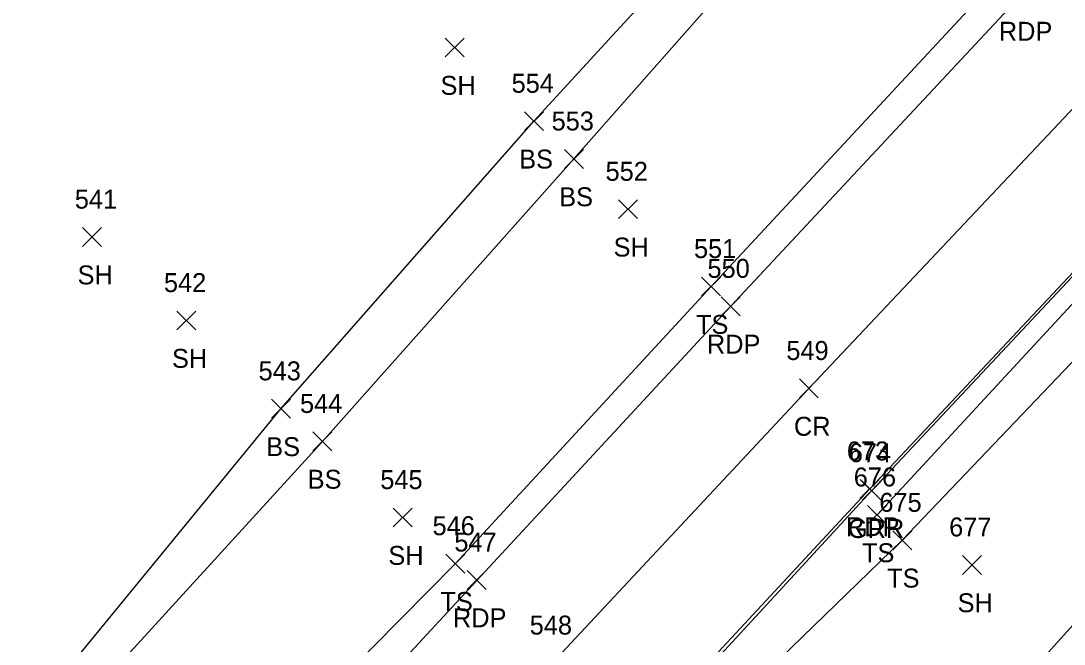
# Model space of a CAD drawing. Extents: x 1688195 to 1692013, y 424605 to 441234.
# Drawn here: x 1691404.7 to 1691514.7, y 438975.6 to 439041.4 of the extents above; entities that cross this region are included whole.
import ezdxf

# ---------------------------------------------------------------- set-up
doc = ezdxf.new("R2010")
doc.units = 0
for name, color, linetype in [('L_A', 7, 'Continuous'), ('L_I', 7, 'Continuous'), ('L_TIC', 7, 'Continuous'), ('LELB', 7, 'Continuous'), ('LFNC', 7, 'Continuous'), ('P_A', 7, 'Continuous'), ('P_I', 7, 'Continuous'), ('P_TIC', 7, 'Continuous'), ('PET', 7, 'Continuous'), ('PRC', 7, 'Continuous'), ('R_A', 7, 'Continuous'), ('R_I', 7, 'Continuous'), ('R_TIC', 7, 'Continuous'), ('RGR', 7, 'Continuous')]:
    doc.layers.add(name, color=color, linetype=linetype)

msp = doc.modelspace()

# ---------------------------------------------------------------- linework, layer by layer
at = {"layer": 'L_TIC'}
for points in [[(1691449.43, 439037.57), (1691451.43, 439039.57)], [(1691451.43, 439037.57), (1691449.43, 439039.57)], [(1691457.78, 439029.79), (1691459.78, 439031.79)], [(1691459.78, 439029.79), (1691457.78, 439031.79)], [(1691462, 439025.81), (1691464, 439027.81)], [(1691464, 439025.81), (1691462, 439027.81)], [(1691467.69, 439020.5), (1691469.69, 439022.5)], [(1691469.69, 439020.5), (1691467.69, 439022.5)], [(1691411.15, 439017.56), (1691413.15, 439019.56)], [(1691413.15, 439017.56), (1691411.15, 439019.56)], [(1691476.46, 439012.34), (1691478.46, 439014.34)], [(1691478.46, 439012.34), (1691476.46, 439014.34)], [(1691421.12, 439008.75), (1691423.12, 439010.75)], [(1691423.12, 439008.75), (1691421.12, 439010.75)], [(1691431.09, 438999.43), (1691433.09, 439001.43)], [(1691433.09, 438999.43), (1691431.09, 439001.43)], [(1691435.47, 438995.99), (1691437.47, 438997.99)], [(1691437.47, 438995.99), (1691435.47, 438997.99)], [(1691493.97, 438988.23), (1691495.97, 438990.23)], [(1691495.97, 438988.23), (1691493.97, 438990.23)], [(1691443.94, 438987.95), (1691445.94, 438989.95)], [(1691445.94, 438987.95), (1691443.94, 438989.95)], [(1691496.62, 438985.55), (1691498.62, 438987.55)], [(1691498.62, 438985.55), (1691496.62, 438987.55)], [(1691496.62, 438985.55), (1691498.62, 438987.55)], [(1691498.62, 438985.55), (1691496.62, 438987.55)], [(1691449.5, 438983.08), (1691451.5, 438985.08)], [(1691451.5, 438983.08), (1691449.5, 438985.08)], [(1691503.97, 438982.95), (1691505.97, 438984.95)], [(1691505.97, 438982.95), (1691503.97, 438984.95)]]:
    msp.add_lwpolyline(points, dxfattribs=at)
at = {"layer": 'LELB'}
for points in [[(1691372.73, 438902.64), (1691398.57, 438929.63), (1691421.61, 438954.81), (1691450.5, 438984.08), (1691477.46, 439013.34), (1691508.26, 439046.52), (1691540.85, 439082.44), (1691568.31, 439110.72), (1691593.69, 439141.21), (1691622.93, 439171.73), (1691652.84, 439206.76), (1691674.71, 439229.19), (1691701.22, 439256.48), (1691710.89, 439279.75), (1691723.95, 439307.99), (1691712.17, 439332.07), (1691693.94, 439358.26), (1691684, 439373.02)], [(1691358.65, 438915.95), (1691383.88, 438942.54), (1691406.19, 438968.83), (1691432.09, 439000.43), (1691458.78, 439030.79), (1691488.91, 439063.66), (1691516.55, 439102.83), (1691546.52, 439127.21), (1691571.44, 439162.09), (1691585.36, 439179.75), (1691595.61, 439189.84), (1691598.8, 439192.56), (1691623.09, 439224.33), (1691645.87, 439250.99)], [(1691362.51, 438912.64), (1691386.93, 438940.67), (1691409.23, 438967.09), (1691436.47, 438996.99), (1691463, 439026.81), (1691492.43, 439060.22), (1691523.16, 439097.82), (1691549.35, 439125.66), (1691575.52, 439158.24), (1691588.61, 439176.65), (1691597.67, 439188.52), (1691599.59, 439192.01), (1691624.28, 439223.08), (1691646.72, 439249.94), (1691645.87, 439250.99)], [(1691494.97, 438989.23), (1691529.39, 439026.47), (1691563.11, 439061.46), (1691592.32, 439093.25), (1691622.45, 439123.57), (1691640.28, 439144.55), (1691642.63, 439146.18), (1691644.54, 439148.64), (1691657.14, 439160.25), (1691677.5, 439185.53), (1691687.79, 439198.06), (1691700.53, 439206.6), (1691711.71, 439214.4), (1691729.93, 439221), (1691765.22, 439228.65), (1691785.8, 439230.06)], [(1691497.62, 438986.55), (1691532.48, 439023.13), (1691565.52, 439059.1), (1691594.4, 439089.96), (1691624.94, 439121.84), (1691642.24, 439143.61)], [(1691395.27, 438879.71), (1691419.93, 438903.79), (1691447.01, 438933.65), (1691476.59, 438966.16), (1691497.62, 438986.55)]]:
    msp.add_lwpolyline(points, dxfattribs=at)
at = {"layer": 'LFNC'}
msp.add_lwpolyline([(1691844.63, 439219.19), (1691827.3, 439208.18), (1691808.98, 439197.07), (1691805.18, 439194.78), (1691802.65, 439193.15), (1691780.93, 439179.95), (1691740.49, 439155.55), (1691707.63, 439134.9), (1691682.09, 439120.04), (1691638.96, 439093.47), (1691599.84, 439067.34), (1691566.38, 439033.38), (1691536.95, 439001.22), (1691500.89, 438961.26), (1691462.91, 438919.55), (1691429.39, 438883.14), (1691411.26, 438863.12)], dxfattribs=at)
at = {"layer": 'P_TIC'}
for points in [[(1691478.53, 439010.25), (1691480.53, 439012.25)], [(1691480.53, 439010.25), (1691478.53, 439012.25)], [(1691486.77, 439001.58), (1691488.77, 439003.58)], [(1691488.77, 439001.58), (1691486.77, 439003.58)], [(1691493.19, 438990.98), (1691495.19, 438992.98)], [(1691495.19, 438990.98), (1691493.19, 438992.98)], [(1691451.74, 438981.36), (1691453.74, 438983.36)], [(1691453.74, 438981.36), (1691451.74, 438983.36)]]:
    msp.add_lwpolyline(points, dxfattribs=at)
at = {"layer": 'PET'}
for points in [[(1691375.46, 438899.9), (1691401.5, 438927.23), (1691424.19, 438951.44), (1691479.53, 439011.25), (1691510.32, 439044.28), (1691543.27, 439079.53), (1691570.24, 439108.89), (1691596.97, 439137.86), (1691630.02, 439173.34), (1691657.32, 439202.46), (1691678.85, 439225.99), (1691705.09, 439253.29), (1691720.65, 439270.18), (1691741.75, 439292.31), (1691750.04, 439301.33), (1691750.82, 439305.81), (1691750.97, 439309.53)], [(1691392.15, 438883.12), (1691415.43, 438907.79), (1691443.51, 438937.17), (1691473.2, 438969.34), (1691494.19, 438991.98), (1691527.98, 439028.02), (1691561.01, 439063.43)]]:
    msp.add_lwpolyline(points, dxfattribs=at)
at = {"layer": 'PRC'}
msp.add_lwpolyline([(1691383.45, 438891.46), (1691410.11, 438918.45), (1691432.71, 438943.44), (1691460.69, 438973.59), (1691487.77, 439002.58), (1691519.39, 439036.11), (1691551.83, 439070.88), (1691579.21, 439100.29), (1691605.82, 439129.37), (1691637.88, 439164.38), (1691665.6, 439193.96), (1691687.96, 439216.92), (1691714.01, 439245.27), (1691730.35, 439261.96), (1691750.53, 439284.62), (1691763.38, 439297.71)], dxfattribs=at)
at = {"layer": 'R_TIC'}
for points in [[(1691493.4, 438990.79), (1691495.4, 438992.79)], [(1691495.4, 438990.79), (1691493.4, 438992.79)]]:
    msp.add_lwpolyline(points, dxfattribs=at)
at = {"layer": 'RGR'}
msp.add_lwpolyline([(1691392.43, 438882.91), (1691415.63, 438907.66), (1691443.42, 438937.01), (1691473.56, 438969.15), (1691494.4, 438991.79), (1691528.19, 439027.86), (1691561.17, 439063.3), (1691590.77, 439094.95), (1691620.16, 439126.42), (1691638.64, 439146.14), (1691654.09, 439162.7)], dxfattribs=at)

# ---------------------------------------------------------------- texts
at = {"layer": 'L_A'}
for s, p in [('SH', (1691448.92, 439033.57)), ('BS', (1691457.22, 439025.79)), ('BS', (1691461.44, 439021.81)), ('SH', (1691467.18, 439016.5)), ('SH', (1691410.64, 439013.56)), ('TS', (1691475.87, 439008.34)), ('SH', (1691420.6, 439004.75)), ('BS', (1691430.54, 438995.43)), ('BS', (1691434.91, 438991.99)), ('SH', (1691443.42, 438983.95)), ('TS', (1691493.38, 438984.23)), ('TS', (1691496.03, 438981.55)), ('TS', (1691496.03, 438981.55)), ('TS', (1691448.91, 438979.08)), ('SH', (1691503.46, 438978.95))]:
    msp.add_text(s, height=2, dxfattribs=at).set_placement(p)
at = {"layer": 'L_I'}
for s, p in [('554', (1691456.42, 439033.79)), ('553', (1691460.64, 439029.81)), ('552', (1691466.33, 439024.5)), ('541', (1691410.35, 439021.56)), ('551', (1691475.66, 439016.34)), ('542', (1691419.75, 439012.75)), ('543', (1691429.73, 439003.43)), ('544', (1691434.1, 438999.99)), ('545', (1691442.57, 438991.95)), ('676', (1691492.51, 438992.23)), ('675', (1691495.21, 438989.55)), ('675', (1691495.21, 438989.55)), ('546', (1691448.08, 438987.08)), ('677', (1691502.57, 438986.95))]:
    msp.add_text(s, height=2, dxfattribs=at).set_placement(p)
at = {"layer": 'P_A'}
for s, p in [('RDP', (1691507.81, 439039.28)), ('RDP', (1691477.02, 439006.25)), ('CR', (1691486.2, 438997.58)), ('RDP', (1691491.68, 438986.98)), ('RDP', (1691450.23, 438977.36))]:
    msp.add_text(s, height=2, dxfattribs=at).set_placement(p)
at = {"layer": 'P_I'}
for s, p in [('550', (1691477.08, 439014.25)), ('549', (1691485.4, 439005.58)), ('673', (1691491.78, 438994.98)), ('547', (1691450.38, 438985.36)), ('548', (1691458.33, 438976.59))]:
    msp.add_text(s, height=2, dxfattribs=at).set_placement(p)
at = {"layer": 'R_A'}
msp.add_text('GRR', height=2, dxfattribs=at).set_placement((1691491.89, 438986.79))
at = {"layer": 'R_I'}
msp.add_text('674', height=2, dxfattribs=at).set_placement((1691491.99, 438994.79))

doc.saveas('drawing.dxf')
